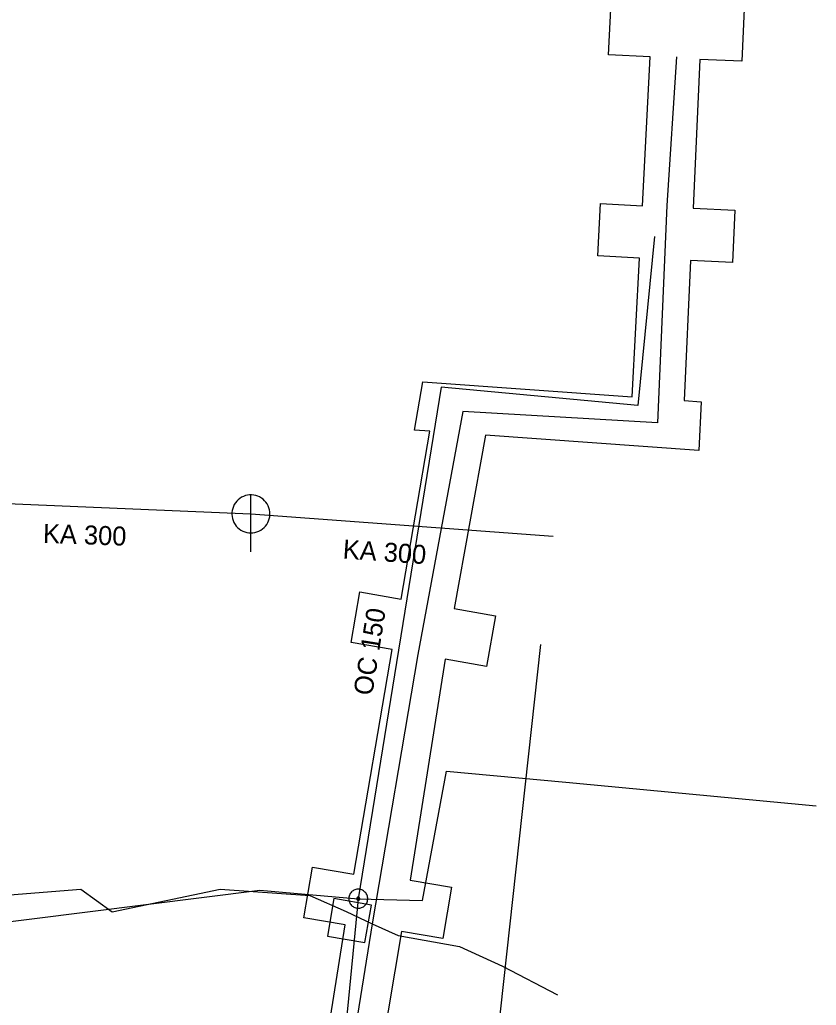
# Model space of a CAD drawing. Extents: x -759784 to -759434, y -974861 to -974639.
# Drawn here: x -759489.5 to -759447.6, y -974742.8 to -974691 of the extents above; entities that cross this region are included whole.
import ezdxf

# ---------------------------------------------------------------- set-up
doc = ezdxf.new("R2010")
doc.units = 0
for name, color, linetype in [('IS_CETIN_kolektor', 7, 'Continuous'), ('IS_CETIN_sdělovací kabel_podzemní', 7, 'Continuous'), ('IS_popis_ScVK', 7, 'Continuous'), ('IS_ScVK_Kanal', 7, 'Continuous'), ('IS_ScVK_Vodovod', 7, 'Continuous')]:
    doc.layers.add(name, color=color, linetype=linetype)

msp = doc.modelspace()

# ---------------------------------------------------------------- linework, layer by layer
at = {"layer": 'IS_CETIN_kolektor'}
for points in [[(-759474.9, -974754.36), (-759472.4, -974738.58), (-759474.57, -974738.21), (-759474.11, -974735.55), (-759471.94, -974735.92), (-759469.92, -974724.1), (-759472.08, -974723.73), (-759471.63, -974721.06), (-759469.46, -974721.44), (-759467.95, -974712.61), (-759468.75, -974712.55), (-759468.31, -974710.01), (-759457.3, -974710.8), (-759456.91, -974703.5), (-759459.11, -974703.38), (-759458.96, -974700.64), (-759456.76, -974700.75), (-759456.35, -974692.92), (-759458.54, -974692.81), (-759458.4, -974690.05)], [(-759451.41, -974690.39), (-759451.54, -974693.15), (-759453.74, -974693.05), (-759454.1, -974700.88), (-759451.9, -974700.98), (-759452.03, -974703.73), (-759454.23, -974703.63), (-759454.57, -974710.99), (-759453.67, -974711.06), (-759453.79, -974713.62), (-759465.01, -974712.82), (-759466.66, -974721.94), (-759464.49, -974722.33), (-759464.97, -974724.99), (-759467.14, -974724.6), (-759468.98, -974736.24), (-759466.81, -974736.6), (-759467.26, -974739.3), (-759469.43, -974738.93), (-759472.22, -974755.53)]]:
    msp.add_lwpolyline(points, dxfattribs=at)
msp.add_lwpolyline([(-759472.99, -974737.2), (-759473.331, -974739.171), (-759471.36, -974739.512), (-759471.019, -974737.541)], close=True, dxfattribs=at)
at = {"layer": 'IS_CETIN_sdělovací kabel_podzemní'}
for points in [[(-759454.97, -974692.92), (-759455.48, -974700.73), (-759455.96, -974712.17), (-759466.21, -974711.58), (-759468.57, -974724.36), (-759470.97, -974738.53), (-759473.67, -974755.35), (-759473.56, -974756.95), (-759463.26, -974757.59), (-759462.76, -974765.66), (-759463.72, -974777.99)], [(-759501.2, -974736.28), (-759500.99, -974737.45), (-759498.83, -974737.7), (-759486.31, -974736.7), (-759484.66, -974737.9), (-759478.97, -974736.71), (-759474.26, -974737.04), (-759472.35, -974737.88), (-759470.97, -974738.53), (-759469.61, -974739.15), (-759466.38, -974739.73), (-759464.12, -974740.75), (-759461.22, -974742.26)]]:
    msp.add_lwpolyline(points, dxfattribs=at)
at = {"layer": 'IS_ScVK_Kanal'}
for points in [[(-759476.359, -974716.961), (-759476.364, -974716.852), (-759476.382, -974716.744), (-759476.412, -974716.638), (-759476.452, -974716.537), (-759476.504, -974716.44), (-759476.566, -974716.35), (-759476.638, -974716.267), (-759476.718, -974716.193), (-759476.806, -974716.127), (-759476.9, -974716.072), (-759477, -974716.027), (-759477.105, -974715.994), (-759477.212, -974715.972), (-759477.321, -974715.962), (-759477.431, -974715.964), (-759477.539, -974715.978), (-759477.646, -974716.003), (-759477.749, -974716.04), (-759477.847, -974716.089), (-759477.939, -974716.147), (-759478.025, -974716.216), (-759478.102, -974716.293), (-759478.171, -974716.379), (-759478.23, -974716.471), (-759478.278, -974716.569), (-759478.315, -974716.672), (-759478.341, -974716.779), (-759478.355, -974716.887), (-759478.358, -974716.997), (-759478.348, -974717.106), (-759478.327, -974717.213), (-759478.293, -974717.317), (-759478.249, -974717.417), (-759478.194, -974717.512), (-759478.128, -974717.6), (-759478.054, -974717.68), (-759477.971, -974717.752), (-759477.881, -974717.814), (-759477.785, -974717.866), (-759477.683, -974717.907), (-759477.578, -974717.937), (-759477.47, -974717.955), (-759477.36, -974717.961), (-759477.251, -974717.955), (-759477.143, -974717.937), (-759477.038, -974717.908), (-759476.936, -974717.867), (-759476.839, -974717.815), (-759476.749, -974717.753), (-759476.666, -974717.682), (-759476.591, -974717.602), (-759476.526, -974717.514), (-759476.47, -974717.42), (-759476.426, -974717.32), (-759476.392, -974717.216), (-759476.37, -974717.108), (-759476.36, -974716.999), (-759476.359, -974716.961)], [(-759477.359, -974718.961), (-759477.358, -974715.961)], [(-759493.097, -974716.3), (-759477.359, -974716.961)], [(-759477.359, -974716.961), (-759461.46, -974718.139)], [(-759462.129, -974723.827), (-759464.723, -974747.469)]]:
    msp.add_lwpolyline(points, dxfattribs=at)
at = {"layer": 'IS_ScVK_Vodovod'}
for points in [[(-759456.125, -974702.373), (-759457.011, -974711.263), (-759467.346, -974710.298), (-759471.711, -974737.208)], [(-759471.711, -974737.208), (-759468.335, -974737.307), (-759467.068, -974730.491), (-759460.794, -974731.072), (-759447.615, -974732.323)], [(-759520.172, -974738.658), (-759494.905, -974739.024), (-759476.881, -974736.765), (-759471.711, -974737.208)], [(-759471.63, -974736.714), (-759471.682, -974736.709), (-759471.735, -974736.708), (-759471.786, -974736.714), (-759471.838, -974736.724), (-759471.888, -974736.74), (-759471.936, -974736.762), (-759471.981, -974736.788), (-759472.023, -974736.818), (-759472.062, -974736.853), (-759472.098, -974736.891), (-759472.129, -974736.934), (-759472.155, -974736.979), (-759472.177, -974737.027), (-759472.193, -974737.077), (-759472.204, -974737.127), (-759472.209, -974737.179), (-759472.21, -974737.232), (-759472.204, -974737.284), (-759472.194, -974737.335), (-759472.178, -974737.385), (-759472.156, -974737.433), (-759472.13, -974737.479), (-759472.1, -974737.521), (-759472.066, -974737.56), (-759472.027, -974737.595), (-759471.984, -974737.626), (-759471.939, -974737.653), (-759471.891, -974737.674), (-759471.841, -974737.69), (-759471.791, -974737.701), (-759471.739, -974737.706), (-759471.686, -974737.707), (-759471.634, -974737.702), (-759471.583, -974737.691), (-759471.533, -974737.675), (-759471.485, -974737.654), (-759471.439, -974737.628), (-759471.397, -974737.598), (-759471.358, -974737.563), (-759471.323, -974737.524), (-759471.292, -974737.481), (-759471.265, -974737.437), (-759471.244, -974737.388), (-759471.228, -974737.338), (-759471.217, -974737.288), (-759471.212, -974737.236), (-759471.211, -974737.183), (-759471.216, -974737.132), (-759471.227, -974737.08), (-759471.243, -974737.03), (-759471.264, -974736.982), (-759471.29, -974736.937), (-759471.32, -974736.895), (-759471.356, -974736.856), (-759471.394, -974736.82), (-759471.437, -974736.789), (-759471.481, -974736.763), (-759471.53, -974736.741), (-759471.58, -974736.725), (-759471.63, -974736.714)], [(-759471.711, -974737.208), (-759473.653, -974757.27), (-759462.636, -974757.977)], [(-759471.697, -974737.127), (-759471.706, -974737.125), (-759471.714, -974737.126), (-759471.723, -974737.127), (-759471.731, -974737.128), (-759471.74, -974737.131), (-759471.747, -974737.135), (-759471.755, -974737.138), (-759471.762, -974737.143), (-759471.768, -974737.15), (-759471.774, -974737.156), (-759471.779, -974737.163), (-759471.783, -974737.17), (-759471.787, -974737.178), (-759471.79, -974737.185), (-759471.791, -974737.194), (-759471.793, -974737.203), (-759471.792, -974737.211), (-759471.791, -974737.22), (-759471.79, -974737.228), (-759471.787, -974737.237), (-759471.783, -974737.244), (-759471.78, -974737.252), (-759471.775, -974737.259), (-759471.769, -974737.266), (-759471.762, -974737.271), (-759471.755, -974737.276), (-759471.748, -974737.28), (-759471.74, -974737.284), (-759471.733, -974737.287), (-759471.724, -974737.288), (-759471.715, -974737.29), (-759471.707, -974737.289), (-759471.698, -974737.288), (-759471.69, -974737.287), (-759471.681, -974737.284), (-759471.674, -974737.281), (-759471.666, -974737.277), (-759471.659, -974737.272), (-759471.652, -974737.266), (-759471.647, -974737.259), (-759471.642, -974737.252), (-759471.638, -974737.245), (-759471.634, -974737.237), (-759471.631, -974737.23), (-759471.63, -974737.221), (-759471.628, -974737.212), (-759471.629, -974737.204), (-759471.63, -974737.195), (-759471.631, -974737.187), (-759471.634, -974737.178), (-759471.637, -974737.171), (-759471.641, -974737.163), (-759471.646, -974737.156), (-759471.653, -974737.15), (-759471.659, -974737.144), (-759471.666, -974737.139), (-759471.673, -974737.135), (-759471.681, -974737.131), (-759471.688, -974737.128), (-759471.697, -974737.127)]]:
    msp.add_lwpolyline(points, dxfattribs=at)

# ---------------------------------------------------------------- texts
at = {"layer": 'IS_popis_ScVK'}
for s, rotation, p in [('KA 300', 358, (-759488.308, -974718.487)), ('KA 300', 356, (-759472.547, -974719.307)), ('OC 150', 81, (-759470.981, -974726.557))]:
    msp.add_text(s, height=1, rotation=rotation, dxfattribs=at).set_placement(p)

doc.saveas('drawing.dxf')
